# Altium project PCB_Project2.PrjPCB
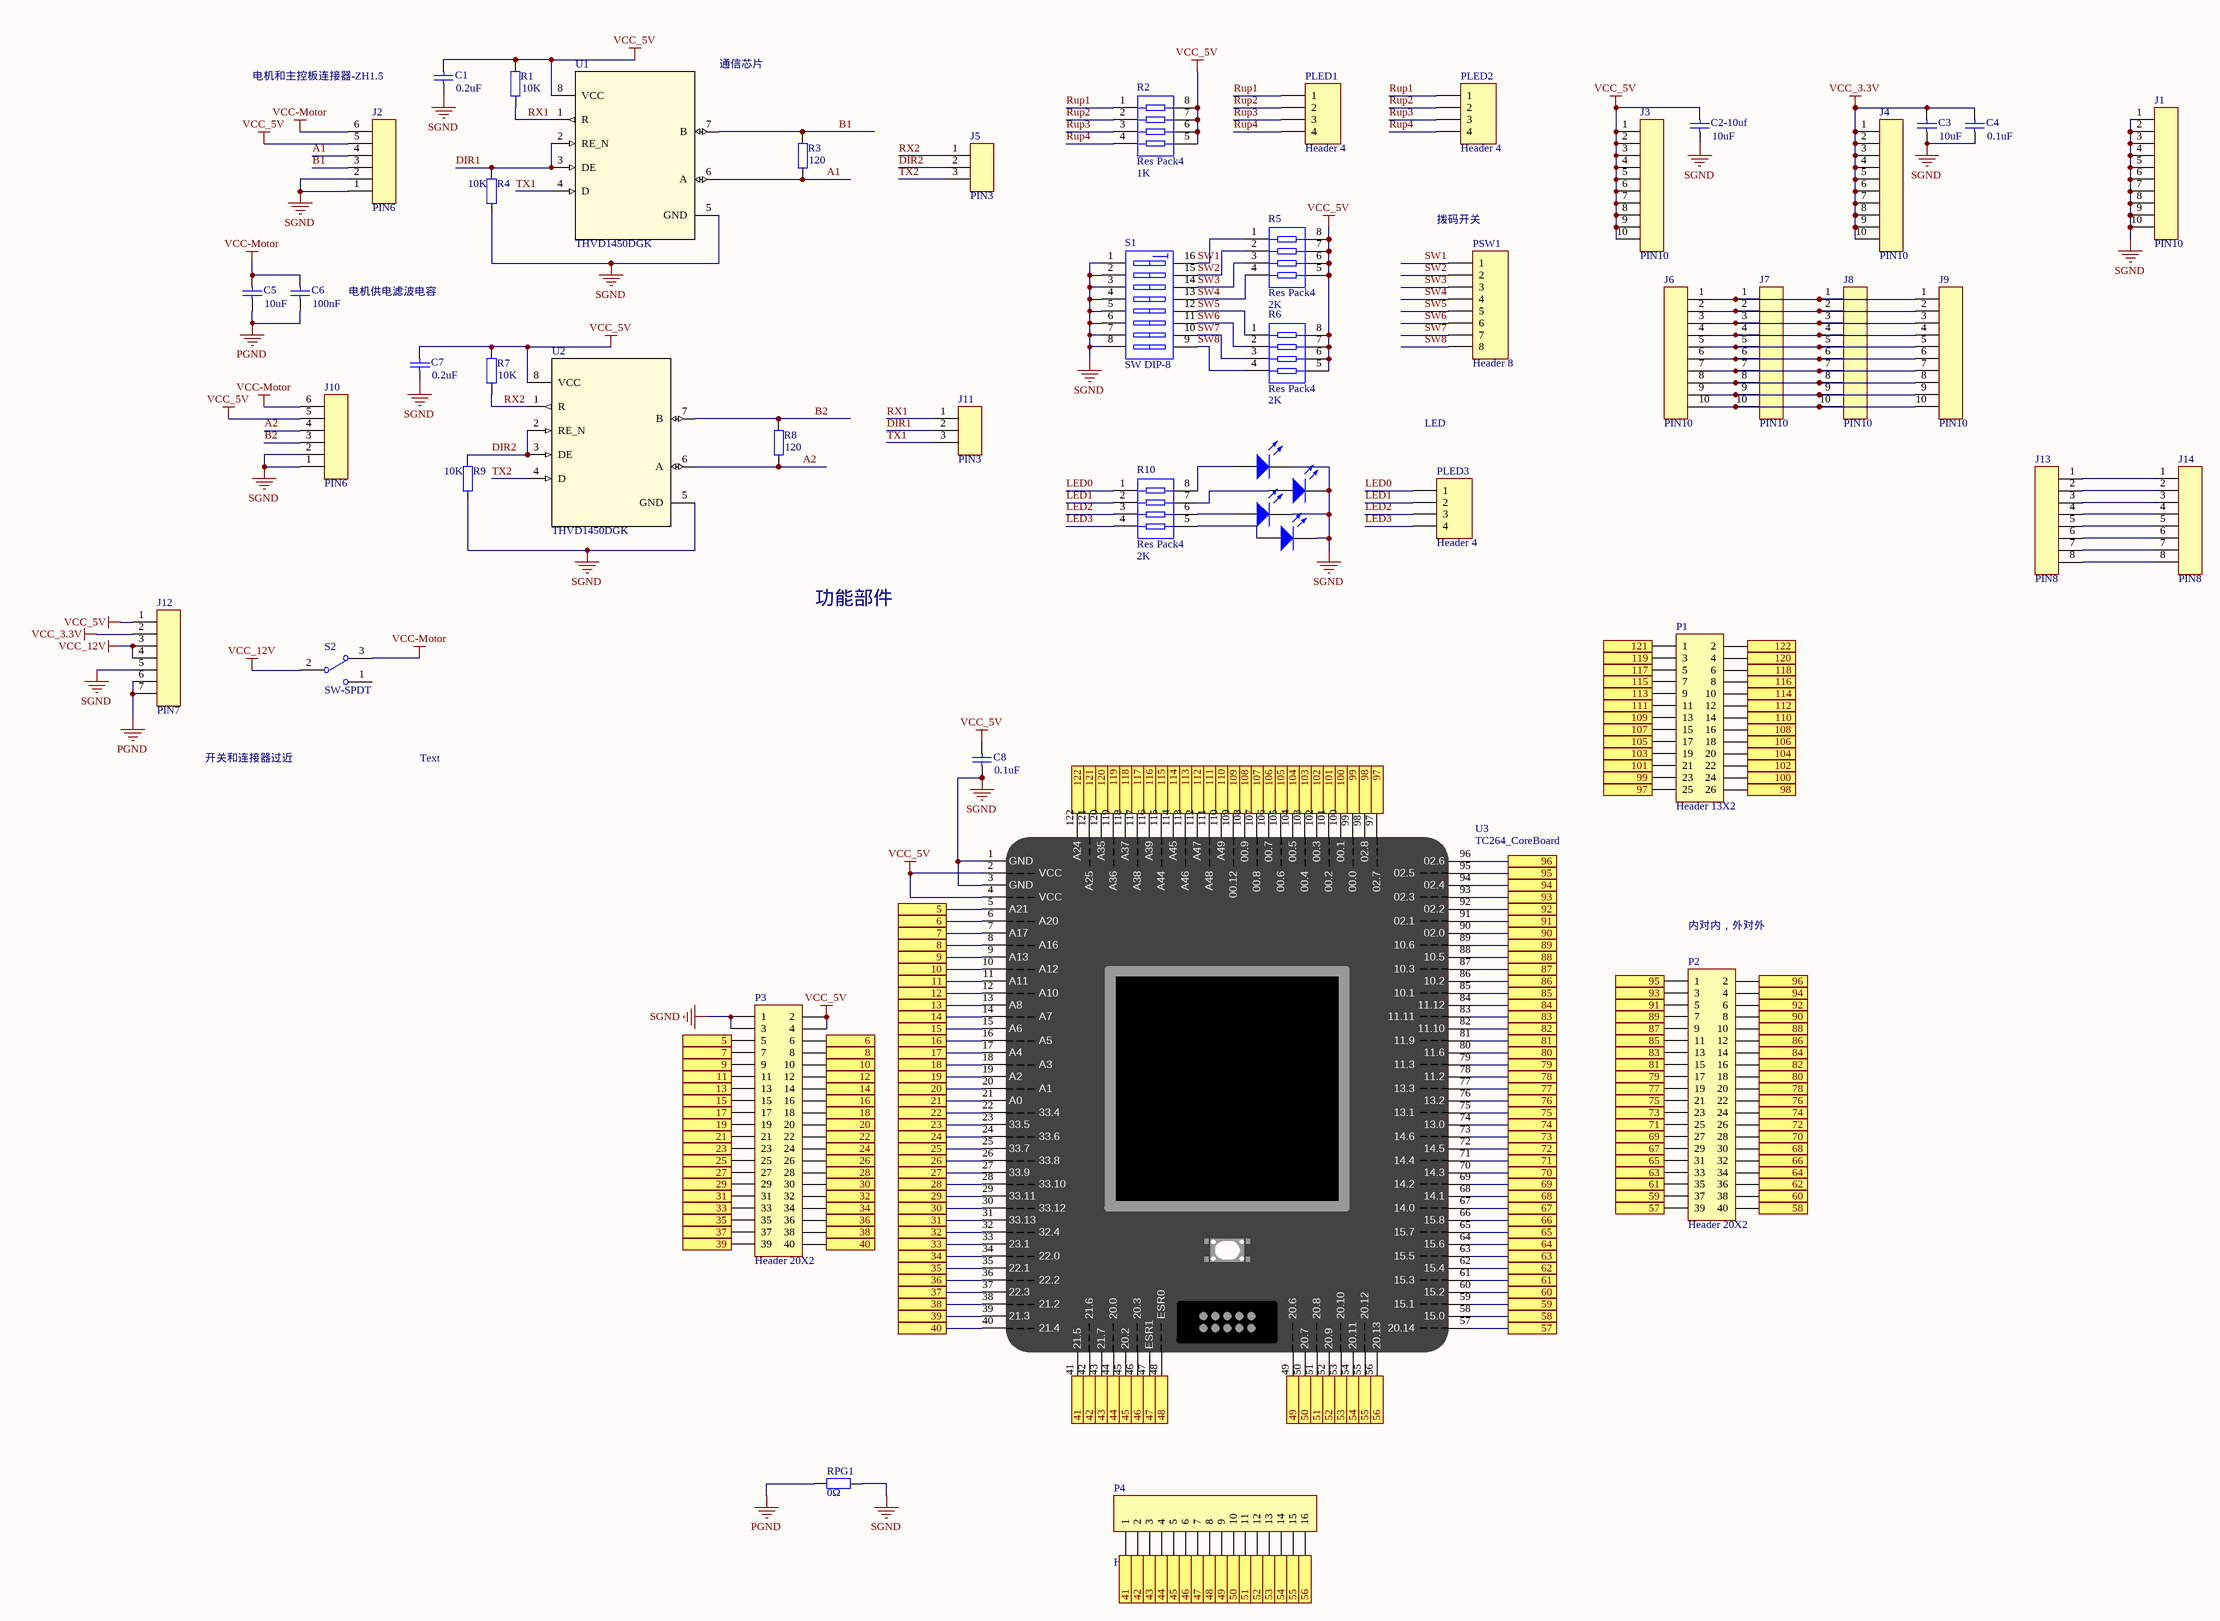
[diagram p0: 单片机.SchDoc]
1 sheet, 50 parts. Net scope: flat (ports and power ports of the same name join across sheets).
Board file: single-chip.PcbDoc

## Sheet 单片机.SchDoc
size C

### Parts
C1  value 0.2uF  [C0805]  (hidden comment: Cap)
C2-10uf  value 10uF  [C0805]  (hidden comment: Cap)
C3  value 10uF  [C0805]  (hidden comment: Cap)
C4  value 0.1uF  [C0805]  (hidden comment: Cap)
C5  value 10uF  [C0805]  (hidden comment: Cap)
C6  value 100nF  [C0805]  (hidden comment: Cap)
C7  value 0.2uF  [C0805]  (hidden comment: Cap)
C8  value 0.1uF  [C0805]  (hidden comment: Cap)
D1  LED0  [LED0805]  (value not drawn)
D2  LED0  [LED0805]  (value not drawn)
D3  LED0  [LED0805]  (value not drawn)
D4  LED0  [LED0805]  (value not drawn)
J1  PIN10  [SIP10]
J2  PIN6  [ZH1.5-LI-6P]
J3  PIN10  [SIP10]
J4  PIN10  [SIP10]
J5  PIN3  [SIP3]
J6  PIN10  [SIP10]
J7  PIN10  [SIP10]
J8  PIN10  [SIP10]
J9  PIN10  [SIP10]
J10  PIN6  [ZH1.5-LI-6P]
J11  PIN3  [SIP3]
J12  PIN7  [XH7-2.54]
J13  PIN8  [SIP8]
J14  PIN8  [SIP8]
P1  Header 13X2  [HDR2X13]
P2  Header 20X2  [HDR2X20]
P3  Header 20X2  [HDR2X20]
P4  Header 16  [HDR1X16]
PLED1  Header 4  [HDR1X4]
PLED2  Header 4  [HDR1X4]
PLED3  Header 4  [HDR1X4]
PSW1  Header 8  [HDR1X8]
R1  value 10K  [R0603]  (hidden comment: Res2)
R2  Res Pack4  value 1K  [R0603 组排]
R3  value 120  [R0603]  (hidden comment: Res2)
R4  value 10K  [R0603]  (hidden comment: Res2)
R5  Res Pack4  value 2K  [R0603 组排]
R6  Res Pack4  value 2K  [R0603 组排]
R7  value 10K  [R0603]  (hidden comment: Res2)
R8  value 120  [R0603]  (hidden comment: Res2)
R9  value 10K  [R0603]  (hidden comment: Res2)
R10  Res Pack4  value 2K  [R0603 组排]
RPG1  value 0Ω  [R1206]  (hidden comment: Res2)
S1  SW DIP-8  [DIP_SW_8WAY_SMD]
S2  SW-SPDT  [SW-TO3]
U1  THVD1450DGK  [DGK0008A_N]
U2  THVD1450DGK  [DGK0008A_N]
U3  TC264_CoreBoard  [TC264_CoreBoard]

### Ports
5, 6, 7, 8, 9, 10, 11, 12, 13, 14, 15, 16, 17, 18, 19, 20, 21, 22, 23, 24, 25, 26, 27, 28, 29, 30, 31, 32, 33, 34, 35, 36, 37, 38, 39, 40, 41, 42, 43, 44, 45, 46, 47, 48, 49, 50, 51, 52, 53, 54, 55, 56, 57, 58, 59, 60, 61, 62, 63, 64, 65, 66, 67, 68, 69, 70, 71, 72, 73, 74, 75, 76, 77, 78, 79, 80, 81, 82, 83, 84, 85, 86, 87, 88, 89, 90, 91, 92, 93, 94, 95, 96, 97, 98, 99, 100, 101, 102, 103, 104, 105, 106, 107, 108, 109, 110, 111, 112, 113, 114, 115, 116, 117, 118, 119, 120, 121, 122

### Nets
PGND: C5.1 C6.1 J12.6 J12.7 RPG1.2
SGND: C1.1 C2-10uf.1 C3.1 C4.1 C7.1 C8.1 D1.2(K) D2.2(K) D3.2(K) D4.2(K) J1.1 J1.2 J1.3 J1.4 J1.5 J1.6 J1.7 J1.8 J1.9 J1.10 J2.1 J2.2 J10.1 J10.2 J12.5 P3.1 P3.3 R4.1 R9.1 RPG1.1 S1.1(A1) S1.2(A2) S1.3(A3) S1.4(A4) S1.5(A5) S1.6(A6) S1.7(A7) S1.8(A8) U1.5(GND) U2.5(GND) U3.1(GND) U3.3(GND)
VCC-Motor: C5.2 C6.2 J2.6 J10.6 S2.3
VCC_3.3V: C3.2 C4.2 J4.1 J4.2 J4.3 J4.4 J4.5 J4.6 J4.7 J4.8 J4.9 J4.10 J12.2
VCC_5V: C1.2 C2-10uf.2 C7.2 C8.2 J2.5 J3.1 J3.2 J3.3 J3.4 J3.5 J3.6 J3.7 J3.8 J3.9 J3.10 J10.5 J12.1 P3.2 P3.4 R1.2 R2.5 R2.6 R2.7 R2.8 R5.5 R5.6 R5.7 R5.8 R6.5 R6.6 R6.7 R6.8 R7.2 U1.8(VCC) U2.8(VCC) U3.2(VCC) U3.4(VCC)
VCC_12V: J12.3 J12.4 S2.2
A1: J2.4 R3.1 U1.6(A)
A2: J10.4 R8.1 U2.6(A)
B1: J2.3 R3.2 U1.7(B)
B2: J10.3 R8.2 U2.7(B)
DIR1: J11.2 R4.2 U1.2(RE_N) U1.3(DE)
DIR2: J5.2 R9.2 U2.2(RE_N) U2.3(DE)
LED0: PLED3.1 R10.1
LED1: PLED3.2 R10.2
LED2: PLED3.3 R10.3
LED3: PLED3.4 R10.4
Rup1: PLED1.1 PLED2.1 R2.1
Rup2: PLED1.2 PLED2.2 R2.2
Rup3: PLED1.3 PLED2.3 R2.3
Rup4: PLED1.4 PLED2.4 R2.4
RX1: J11.1 R1.1 U1.1(R)
RX2: J5.1 R7.1 U2.1(R)
SW1: PSW1.1 R5.1 S1.16(B1)
SW2: PSW1.2 R5.2 S1.15(B2)
SW3: PSW1.3 R5.3 S1.14(B3)
SW4: PSW1.4 R5.4 S1.13(B4)
SW5: PSW1.5 R6.1 S1.12(B5)
SW6: PSW1.6 R6.2 S1.11(B6)
SW7: PSW1.7 R6.3 S1.10(B7)
SW8: PSW1.8 R6.4 S1.9(B8)
TX1: J11.3 U1.4(D)
TX2: J5.3 U2.4(D)
NetD1_1: D1.1(A) R10.8
NetD2_1: D2.1(A) R10.7
NetD3_1: D3.1(A) R10.6
NetD4_1: D4.1(A) R10.5
NetJ6_1: J6.1 J7.1 J8.1 J9.1
NetJ6_2: J6.2 J7.2 J8.2 J9.2
NetJ6_3: J6.3 J7.3 J8.3 J9.3
NetJ6_4: J6.4 J7.4 J8.4 J9.4
NetJ6_5: J6.5 J7.5 J8.5 J9.5
NetJ6_6: J6.6 J7.6 J8.6 J9.6
NetJ6_7: J6.7 J7.7 J8.7 J9.7
NetJ6_8: J6.8 J7.8 J8.8 J9.8
NetJ6_9: J6.9 J7.9 J8.9 J9.9
NetJ6_10: J6.10 J7.10 J8.10 J9.10
NetJ13_1: J13.1 J14.1
NetJ13_2: J13.2 J14.2
NetJ13_3: J13.3 J14.3
NetJ13_4: J13.4 J14.4
NetJ13_5: J13.5 J14.5
NetJ13_6: J13.6 J14.6
NetJ13_7: J13.7 J14.7
NetJ13_8: J13.8 J14.8
NetP1_1: P1.1 U3.121(A25) ; port 121
NetP1_2: P1.2 U3.122(A24) ; port 122
NetP1_3: P1.3 U3.119(A36) ; port 119
NetP1_4: P1.4 U3.120(A35) ; port 120
NetP1_5: P1.5 U3.117(A38) ; port 117
NetP1_6: P1.6 U3.118(A37) ; port 118
NetP1_7: P1.7 U3.115(A44) ; port 115
NetP1_8: P1.8 U3.116(A39) ; port 116
NetP1_9: P1.9 U3.113(A46) ; port 113
NetP1_10: P1.10 U3.114(A45) ; port 114
NetP1_11: P1.11 U3.111(A48) ; port 111
NetP1_12: P1.12 U3.112(A47) ; port 112
NetP1_13: P1.13 U3.109(00.12) ; port 109
NetP1_14: P1.14 U3.110(A49) ; port 110
NetP1_15: P1.15 U3.107(00.8) ; port 107
NetP1_16: P1.16 U3.108(00.9) ; port 108
NetP1_17: P1.17 U3.105(00.6) ; port 105
NetP1_18: P1.18 U3.106(00.7) ; port 106
NetP1_19: P1.19 U3.103(00.4) ; port 103
NetP1_20: P1.20 U3.104(00.5) ; port 104
NetP1_21: P1.21 U3.101(00.2) ; port 101
NetP1_22: P1.22 U3.102(00.3) ; port 102
NetP1_23: P1.23 U3.99(00.0) ; port 99
NetP1_24: P1.24 U3.100(00.1) ; port 100
NetP1_25: P1.25 U3.97(02.7) ; port 97
NetP1_26: P1.26 U3.98(02.8) ; port 98
NetP2_1: P2.1 U3.95(02.5) ; port 95
NetP2_2: P2.2 U3.96(02.6) ; port 96
NetP2_3: P2.3 U3.93(02.3) ; port 93
NetP2_4: P2.4 U3.94(02.4) ; port 94
NetP2_5: P2.5 U3.91(02.1) ; port 91
NetP2_6: P2.6 U3.92(02.2) ; port 92
NetP2_7: P2.7 U3.89(10.6) ; port 89
NetP2_8: P2.8 U3.90(02.0) ; port 90
NetP2_9: P2.9 U3.87(10.3) ; port 87
NetP2_10: P2.10 U3.88(10.5) ; port 88
NetP2_11: P2.11 U3.85(10.1) ; port 85
NetP2_12: P2.12 U3.86(10.2) ; port 86
NetP2_13: P2.13 U3.83(11.11) ; port 83
NetP2_14: P2.14 U3.84(11.12) ; port 84
NetP2_15: P2.15 U3.81(11.9) ; port 81
NetP2_16: P2.16 U3.82(11.10) ; port 82
NetP2_17: P2.17 U3.79(11.3) ; port 79
NetP2_18: P2.18 U3.80(11.6) ; port 80
NetP2_19: P2.19 U3.77(13.3) ; port 77
NetP2_20: P2.20 U3.78(11.2) ; port 78
NetP2_21: P2.21 U3.75(13.1) ; port 75
NetP2_22: P2.22 U3.76(13.2) ; port 76
NetP2_23: P2.23 U3.73(14.6) ; port 73
NetP2_24: P2.24 U3.74(13.0) ; port 74
NetP2_25: P2.25 U3.71(14.4) ; port 71
NetP2_26: P2.26 U3.72(14.5) ; port 72
NetP2_27: P2.27 U3.69(14.2) ; port 69
NetP2_28: P2.28 U3.70(14.3) ; port 70
NetP2_29: P2.29 U3.67(14.0) ; port 67
NetP2_30: P2.30 U3.68(14.1) ; port 68
NetP2_31: P2.31 U3.65(15.7) ; port 65
NetP2_32: P2.32 U3.66(15.8) ; port 66
NetP2_33: P2.33 U3.63(15.5) ; port 63
NetP2_34: P2.34 U3.64(15.6) ; port 64
NetP2_35: P2.35 U3.61(15.3) ; port 61
NetP2_36: P2.36 U3.62(15.4) ; port 62
NetP2_37: P2.37 U3.59(15.1) ; port 59
NetP2_38: P2.38 U3.60(15.2) ; port 60
NetP2_39: P2.39 U3.57(20.14) ; port 57
NetP2_40: P2.40 U3.58(15.0) ; port 58
NetP3_5: P3.5 U3.5(A21) ; port 5
NetP3_6: P3.6 U3.6(A20) ; port 6
NetP3_7: P3.7 U3.7(A17) ; port 7
NetP3_8: P3.8 U3.8(A16) ; port 8
NetP3_9: P3.9 U3.9(A13) ; port 9
NetP3_10: P3.10 U3.10(A12) ; port 10
NetP3_11: P3.11 U3.11(A11) ; port 11
NetP3_12: P3.12 U3.12(A10) ; port 12
NetP3_13: P3.13 U3.13(A8) ; port 13
NetP3_14: P3.14 U3.14(A7) ; port 14
NetP3_15: P3.15 U3.15(A6) ; port 15
NetP3_16: P3.16 U3.16(A5) ; port 16
NetP3_17: P3.17 U3.17(A4) ; port 17
NetP3_18: P3.18 U3.18(A3) ; port 18
NetP3_19: P3.19 U3.19(A2) ; port 19
NetP3_20: P3.20 U3.20(A1) ; port 20
NetP3_21: P3.21 U3.21(A0) ; port 21
NetP3_22: P3.22 U3.22(33.4) ; port 22
NetP3_23: P3.23 U3.23(33.5) ; port 23
NetP3_24: P3.24 U3.24(33.6) ; port 24
NetP3_25: P3.25 U3.25(33.7) ; port 25
NetP3_26: P3.26 U3.26(33.8) ; port 26
NetP3_27: P3.27 U3.27(33.9) ; port 27
NetP3_28: P3.28 U3.28(33.10) ; port 28
NetP3_29: P3.29 U3.29(33.11) ; port 29
NetP3_30: P3.30 U3.30(33.12) ; port 30
NetP3_31: P3.31 U3.31(33.13) ; port 31
NetP3_32: P3.32 U3.32(32.4) ; port 32
NetP3_33: P3.33 U3.33(23.1) ; port 33
NetP3_34: P3.34 U3.34(22.0) ; port 34
NetP3_35: P3.35 U3.35(22.1) ; port 35
NetP3_36: P3.36 U3.36(22.2) ; port 36
NetP3_37: P3.37 U3.37(22.3) ; port 37
NetP3_38: P3.38 U3.38(21.2) ; port 38
NetP3_39: P3.39 U3.39(21.3) ; port 39
NetP3_40: P3.40 U3.40(21.4) ; port 40
NetP4_1: P4.1 U3.41(21.5) ; port 41
NetP4_2: P4.2 U3.42(21.6) ; port 42
NetP4_3: P4.3 U3.43(21.7) ; port 43
NetP4_4: P4.4 U3.44(20.0) ; port 44
NetP4_5: P4.5 U3.45(20.2) ; port 45
NetP4_6: P4.6 U3.46(20.3) ; port 46
NetP4_7: P4.7 U3.47(ESR1) ; port 47
NetP4_8: P4.8 U3.48(ESR0) ; port 48
NetP4_9: P4.9 U3.49(20.6) ; port 49
NetP4_10: P4.10 U3.50(20.7) ; port 50
NetP4_11: P4.11 U3.51(20.8) ; port 51
NetP4_12: P4.12 U3.52(20.9) ; port 52
NetP4_13: P4.13 U3.53(20.10) ; port 53
NetP4_14: P4.14 U3.54(20.11) ; port 54
NetP4_15: P4.15 U3.55(20.12) ; port 55
NetP4_16: P4.16 U3.56(20.13) ; port 56

Not connected (* = marked no-connect by the designer): S2 1

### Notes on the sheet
- 电机和主控板连接器-ZH1.5
- (near U1) 通信芯片
- (near PSW1) 拨码开关
- 电机供电滤波电容
- LED
- 功能部件
- 开关和连接器过近
- Text
- 内对内，外对外

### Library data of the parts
C1 C2-10uf C3-C8 = Cap: Capacitor
D1-D4 = LED0: Typical INFRARED GaAs LED
P1 = Header 13X2: Header, 13-Pin, Dual row
P2 P3 = Header 20X2: Header, 20-Pin, Dual row
P4 = Header 16: Header, 16-Pin
PLED1-PLED3 = Header 4: Header, 4-Pin
PSW1 = Header 8: Header, 8-Pin
R1 R3 R4 R7-R9 RPG1 = Res2: Resistor
R2 R5 R6 R10 = Res_x4: Isolated Resistor Network
S1 = SW DIP-8: DIP Switch, 8 Position, SPST
S2 = SW-SPDT: SPDT Subminiature Toggle Switch, Right Angle Mounting, Vertical Actuation
U1 U2 = THVD1450DGK: No Description Available; Manufacturer: Texas Instruments; PartNumber: THVD1450DGKR
U3 = TC264_CoreBoard: 逐飞科技TC264核心板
